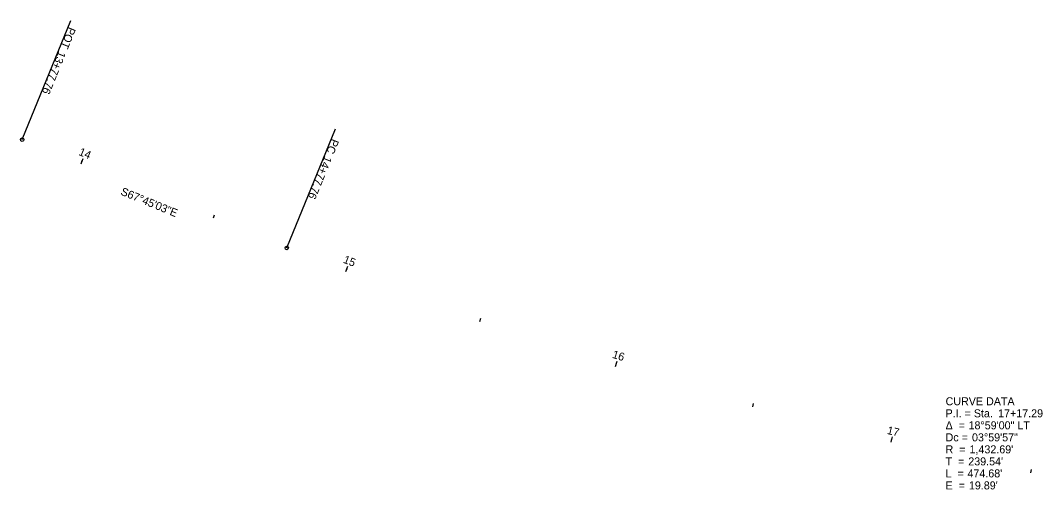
# Model space of a CAD drawing. Extents: x 2273904 to 2275374, y 654586 to 654897.
# Drawn here: x 2273904.1 to 2274261.6, y 654733.5 to 654897.5 of the extents above; entities that cross this region are included whole.
import ezdxf

# ---------------------------------------------------------------- set-up
doc = ezdxf.new("R2010")
doc.units = 0
for name, color, linetype in [('DR_P_Cells', 7, 'Continuous'), ('DR_P_Ditch', 7, 'Continuous'), ('DR_P_Erosion_Control', 7, 'Continuous'), ('GK_Drainage_Nodes', 7, 'Continuous'), ('SC_Scratch1', 7, 'Continuous'), ('SC_Scratch10', 7, 'Continuous')]:
    doc.layers.add(name, color=color, linetype=linetype)

msp = doc.modelspace()

# ---------------------------------------------------------------- linework, layer by layer
at = {"layer": 'DR_P_Ditch'}
for p, q in [((2273904.71, 654855.81), (2273921.75, 654897.46)), ((2273997.27, 654817.95), (2274014.31, 654859.6)), ((2273925.3, 654847.39), (2273925.76, 654848.5)), ((2274017.92, 654809.69), (2274018.65, 654811.55)), ((2274112.25, 654776.55), (2274112.6, 654777.69)), ((2274208.65, 654750.06), (2274208.93, 654751.23))]:
    msp.add_line(p, q, dxfattribs=at)
for centre in [(2273904.71, 654855.81), (2273997.27, 654817.95)]:
    msp.add_circle(centre, 0.6, dxfattribs=at)
at = {"layer": 'DR_P_Erosion_Control'}
for p, q in [((2273904.71, 654855.81), (2273921.75, 654897.46)), ((2273997.27, 654817.95), (2274014.31, 654859.6)), ((2273925.3, 654847.39), (2273926.06, 654849.24)), ((2273971.58, 654828.46), (2273972.03, 654829.57)), ((2274017.92, 654809.69), (2274018.65, 654811.55)), ((2274064.79, 654792.29), (2274065.19, 654793.43)), ((2274112.25, 654776.55), (2274112.84, 654778.45)), ((2274160.22, 654762.46), (2274160.54, 654763.62)), ((2274208.65, 654750.06), (2274209.12, 654752.01)), ((2274257.49, 654739.36), (2274257.73, 654740.53))]:
    msp.add_line(p, q, dxfattribs=at)
for centre in [(2273904.71, 654855.81), (2273997.27, 654817.95)]:
    msp.add_circle(centre, 0.6, dxfattribs=at)
at = {"layer": 'SC_Scratch1'}
for p, q in [((2273904.71, 654855.81), (2273921.75, 654897.46)), ((2273997.27, 654817.95), (2274014.31, 654859.6)), ((2274017.92, 654809.69), (2274018.36, 654810.81))]:
    msp.add_line(p, q, dxfattribs=at)
for centre in [(2273904.71, 654855.81), (2273997.27, 654817.95)]:
    msp.add_circle(centre, 0.6, dxfattribs=at)

# ---------------------------------------------------------------- texts
at = {"layer": 'DR_P_Cells'}
for s, p in [('CURVE DATA', (2274227.69, 654762.98)), ('P.I. = Sta. ', (2274227.69, 654758.78)), ('17+17.29', (2274246.06, 654758.78)), ('Δ  = ', (2274227.69, 654754.58)), ('18°59\'00" LT', (2274235.72, 654754.58)), ('Dc = ', (2274227.69, 654750.38)), ('03°59\'57"', (2274236.93, 654750.38)), ('R  = ', (2274227.69, 654746.18)), ("1,432.69'", (2274236.06, 654746.18)), ('T  = ', (2274227.69, 654741.98)), ("239.54'", (2274235.63, 654741.98)), ('L  = ', (2274227.69, 654737.78)), ("474.68'", (2274235.34, 654737.78)), ('E  = ', (2274227.69, 654733.58)), ("19.89'", (2274235.85, 654733.58))]:
    msp.add_text(s, height=2.8, dxfattribs=at).set_placement(p)
at = {"layer": 'DR_P_Ditch'}
for s, rotation, p in [('POT', 247.751, (2273920.96, 654895.41)), ('13+77.76', 247.751, (2273917.51, 654886.96)), ('PC', 247.751, (2274013.02, 654856.34)), ('14+77.76', 247.751, (2274010.55, 654850.3)), ('15', 338.6404, (2274016.79, 654812.86))]:
    msp.add_text(s, height=2.8, rotation=rotation, dxfattribs=at).set_placement(p)
at = {"layer": 'DR_P_Erosion_Control'}
for s, rotation, p in [('POT', 247.751, (2273920.96, 654895.41)), ('13+77.76', 247.751, (2273917.51, 654886.96)), ('14', 337.751, (2273924.26, 654850.52)), ('PC', 247.751, (2274013.02, 654856.34)), ('14+77.76', 247.751, (2274010.55, 654850.3)), ('15', 338.6404, (2274016.79, 654812.86)), ('16', 342.6396, (2274110.91, 654779.63)), ('17', 346.6388, (2274207.04, 654753.01))]:
    msp.add_text(s, height=2.8, rotation=rotation, dxfattribs=at).set_placement(p)
at = {"layer": 'GK_Drainage_Nodes'}
msp.add_text('S67°45\'03"E', height=2.8, rotation=337.751, dxfattribs=at).set_placement((2273938.93, 654836.63))
msp.add_text('S67°45\'03"E', height=2.8, rotation=337.751, dxfattribs=at).set_placement((2273938.93, 654836.63))
for s, p in [('CURVE DATA', (2274227.69, 654762.98)), ('P.I. = Sta. ', (2274227.69, 654758.78)), ('17+17.29', (2274246.06, 654758.78)), ('Δ  = ', (2274227.69, 654754.58)), ('18°59\'00" LT', (2274235.72, 654754.58)), ('Dc = ', (2274227.69, 654750.38)), ('03°59\'57"', (2274236.93, 654750.38)), ('R  = ', (2274227.69, 654746.18)), ("1,432.69'", (2274236.06, 654746.18)), ('T  = ', (2274227.69, 654741.98)), ("239.54'", (2274235.63, 654741.98)), ('L  = ', (2274227.69, 654737.78)), ("474.68'", (2274235.34, 654737.78)), ('E  = ', (2274227.69, 654733.58)), ("19.89'", (2274235.85, 654733.58))]:
    msp.add_text(s, height=2.8, dxfattribs=at).set_placement(p)
at = {"layer": 'SC_Scratch1'}
for s, p in [('POT', (2273920.96, 654895.41)), ('13+77.76', (2273917.51, 654886.96)), ('PC', (2274013.02, 654856.34)), ('14+77.76', (2274010.55, 654850.3))]:
    msp.add_text(s, height=2.8, rotation=247.751, dxfattribs=at).set_placement(p)
at = {"layer": 'SC_Scratch10'}
msp.add_text('S67°45\'03"E', height=2.8, rotation=337.751, dxfattribs=at).set_placement((2273938.93, 654836.63))
for s, p in [('CURVE DATA', (2274227.69, 654762.98)), ('P.I. = Sta. ', (2274227.69, 654758.78)), ('17+17.29', (2274246.06, 654758.78)), ('Δ  = ', (2274227.69, 654754.58)), ('18°59\'00" LT', (2274235.72, 654754.58)), ('Dc = ', (2274227.69, 654750.38)), ('03°59\'57"', (2274236.93, 654750.38)), ('R  = ', (2274227.69, 654746.18)), ("1,432.69'", (2274236.06, 654746.18)), ('T  = ', (2274227.69, 654741.98)), ("239.54'", (2274235.63, 654741.98)), ('L  = ', (2274227.69, 654737.78)), ("474.68'", (2274235.34, 654737.78)), ('E  = ', (2274227.69, 654733.58)), ("19.89'", (2274235.85, 654733.58))]:
    msp.add_text(s, height=2.8, dxfattribs=at).set_placement(p)

doc.saveas('drawing.dxf')
